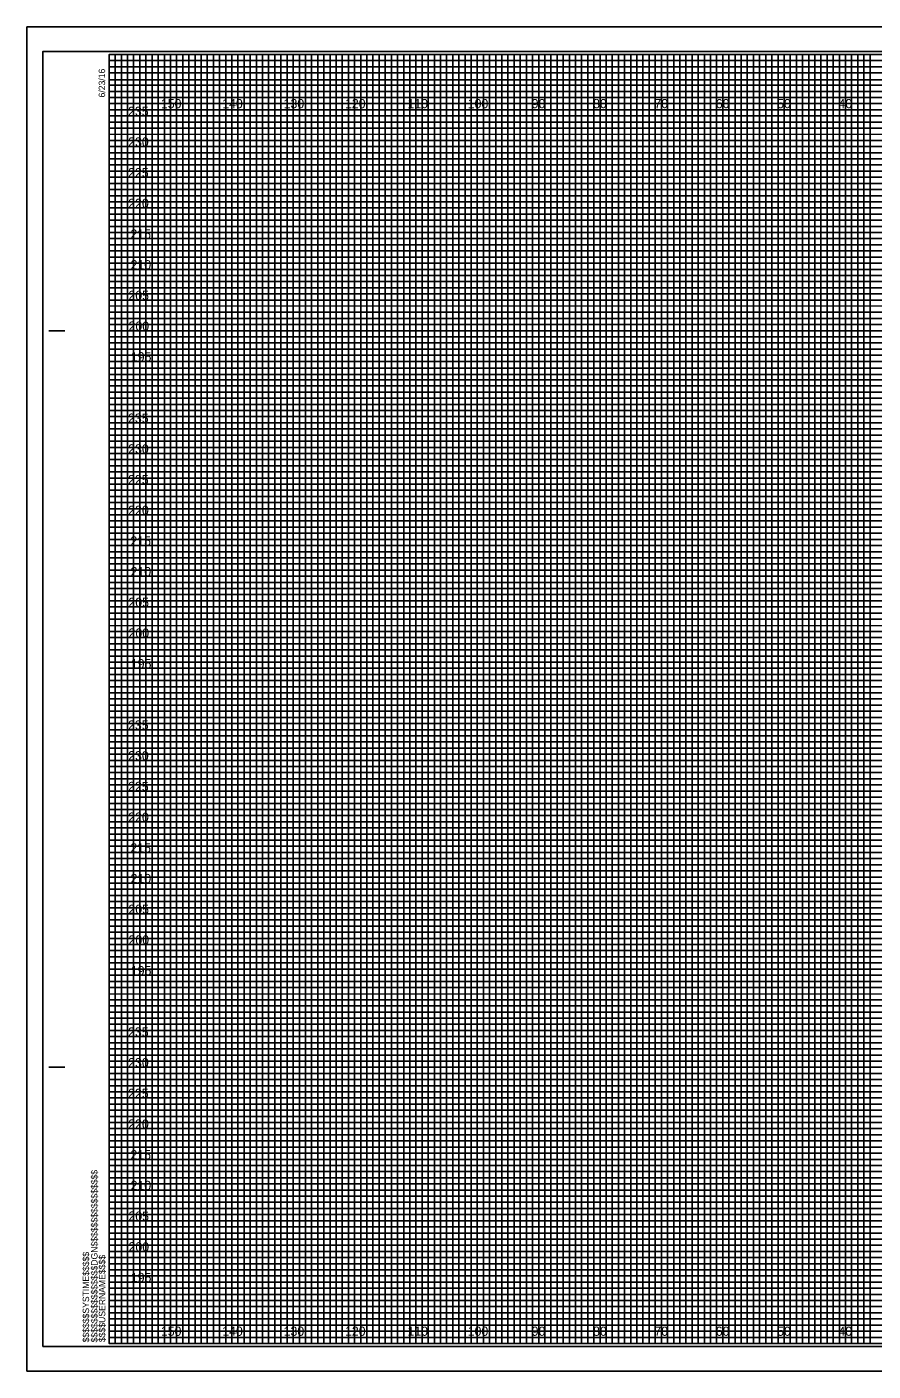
# Model space of a CAD drawing. Extents: x -13 to 323, y -5 to 434.
# Drawn here: x -13.4 to 124.5, y -4.5 to 214.5 of the extents above; entities that cross this region are included whole.
import ezdxf

# ---------------------------------------------------------------- set-up
doc = ezdxf.new("R2010")
doc.units = 0
for name, color, linetype in [('Prop XS Elevation Labels', 7, 'Continuous'), ('Prop XS Offset Labels', 7, 'Continuous'), ('Sheet Cross Section CELL', 7, 'Continuous'), ('Sheet Cross Section Grid Major CELL', 7, 'Continuous'), ('Sheet Cross Section Grid Middle CELL', 7, 'Continuous'), ('Sheet Cross Section Grid Minor 1 CELL', 7, 'Continuous'), ('Sheet Cross Section Grid Minor 2 CELL', 7, 'Continuous'), ('Sheet Cutting Line CELL', 7, 'Continuous'), ('Sheet DOT Grid CELL', 7, 'Continuous'), ('Sheet Plot Border Inside CELL', 7, 'Continuous'), ('Sheet Plot Border Outside CELL', 7, 'Continuous')]:
    doc.layers.add(name, color=color, linetype=linetype)

msp = doc.modelspace()

# ---------------------------------------------------------------- linework, layer by layer
at = {"layer": 'Sheet Cross Section CELL'}
for p, q in [((-9.8, 165), (-7.3, 165)), ((-9.7, 165), (-7.2, 165)), ((-9.8, 45), (-7.3, 45)), ((-9.7, 45), (-7.2, 45)), ((0, 0), (0, 0)), ((0, 0), (0, 0)), ((0, 0), (0, 0)), ((0, 0), (0, 0)), ((0, 0), (0, 0)), ((0, 0), (0, 0)), ((0, 0), (0, 0))]:
    msp.add_line(p, q, dxfattribs=at)
msp.add_lwpolyline([(320, 210), (0, 210), (0, 0), (320, 0)], close=True, dxfattribs=at)
at = {"layer": 'Sheet Cross Section Grid Major CELL'}
for p, q in [((10, 210), (0, 210)), ((10, 0), (10, 210)), ((30, 210), (20, 210)), ((20, 210), (20, 0)), ((30, 0), (30, 210)), ((50, 210), (40, 210)), ((40, 210), (40, 0)), ((50, 0), (50, 210)), ((70, 210), (60, 210)), ((60, 210), (60, 0)), ((70, 0), (70, 210)), ((90, 210), (80, 210)), ((80, 210), (80, 0)), ((90, 0), (90, 210)), ((110, 210), (100, 210)), ((100, 210), (100, 0)), ((110, 0), (110, 210)), ((130, 210), (120, 210)), ((120, 210), (120, 0)), ((20, 0), (10, 0)), ((40, 0), (30, 0)), ((60, 0), (50, 0)), ((80, 0), (70, 0)), ((100, 0), (90, 0)), ((120, 0), (110, 0))]:
    msp.add_line(p, q, dxfattribs=at)
for points in [[(0, 200), (320, 200), (320, 190), (0, 190)], [(0, 180), (320, 180), (320, 170), (0, 170)], [(0, 160), (320, 160), (320, 150), (0, 150)], [(0, 140), (320, 140), (320, 130), (0, 130)], [(0, 120), (320, 120), (320, 110), (0, 110)], [(0, 100), (320, 100), (320, 90), (0, 90)], [(0, 80), (320, 80), (320, 70), (0, 70)], [(0, 60), (320, 60), (320, 50), (0, 50)], [(0, 40), (320, 40), (320, 30), (0, 30)], [(0, 20), (320, 20), (320, 10), (0, 10)]]:
    msp.add_lwpolyline(points, dxfattribs=at)
at = {"layer": 'Sheet Cross Section Grid Middle CELL'}
for points in [[(0, 210), (5, 210), (5, 0), (15, 0), (15, 210), (25, 210), (25, 0), (35, 0), (35, 210), (45, 210), (45, 0), (55, 0), (55, 210), (65, 210), (65, 0), (75, 0), (75, 210), (85, 210), (85, 0), (95, 0), (95, 210), (105, 210), (105, 0), (115, 0), (115, 210), (125, 210)], [(0, 205), (275, 205)], [(0, 185), (320, 185), (320, 195), (0, 195)], [(0, 165), (320, 165), (320, 175), (0, 175)], [(0, 145), (320, 145), (320, 155), (0, 155)], [(0, 125), (320, 125), (320, 135), (0, 135)], [(0, 105), (320, 105), (320, 115), (0, 115)], [(0, 85), (320, 85), (320, 95), (0, 95)], [(0, 65), (320, 65), (320, 75), (0, 75)], [(0, 45), (320, 45), (320, 55), (0, 55)], [(0, 25), (320, 25), (320, 35), (0, 35)], [(0, 5), (320, 5), (320, 15), (0, 15)]]:
    msp.add_lwpolyline(points, dxfattribs=at)
at = {"layer": 'Sheet Cross Section Grid Minor 1 CELL'}
for p, q in [((0, 209), (260, 209)), ((260, 207.98), (0, 207.98)), ((0, 207.98), (0, 207)), ((0, 207), (260, 207)), ((260, 205.89), (0, 205.89)), ((0, 205.89), (0, 204)), ((0, 204), (320, 204))]:
    msp.add_line(p, q, dxfattribs=at)
for points in [[(0, 203), (270, 203), (320, 203), (320, 202), (0, 202)], [(0, 201), (320, 201), (320, 199), (0, 199)], [(0, 198), (320, 198), (320, 197), (0, 196.98)], [(0, 196), (320, 196), (320, 194), (0, 194)], [(0, 193), (320, 193), (320, 192), (0, 192)], [(0, 191), (320, 191), (320, 189), (0, 189)], [(0, 188), (320, 188), (320, 187), (0, 187)], [(0, 186), (320, 186), (320, 184), (0, 184)], [(0, 183), (320, 183), (320, 182), (0, 182)], [(0, 181), (320, 181), (320, 179), (0, 179)], [(0, 178), (320, 178), (320, 177), (0, 177)], [(0, 176), (320, 176), (320, 173.95), (320, 173), (320, 172), (0, 172)], [(0, 174), (320, 174), (320, 173), (0, 173)], [(0, 171), (320, 171), (320, 169), (0, 169.03)], [(0, 169.03), (320, 169), (320, 168), (0, 168)], [(0, 167), (320, 167), (320, 166), (0, 166)], [(0, 164), (320, 164), (320, 163), (0, 163)], [(0, 162), (320, 162), (320, 161), (0, 161)], [(-0.07, 158.89), (320, 158.89), (320, 157.88), (-0.07, 157.88)], [(0, 157), (320, 157), (320, 156), (0, 156)], [(0, 154), (320, 154), (320, 153), (0, 153)], [(0, 152), (320, 152), (320, 151), (0, 151)], [(0, 149), (320, 149), (320, 148), (0, 148)], [(0, 147), (320, 147), (320, 146), (0, 146)], [(0, 144), (320, 144), (320, 143), (0, 143)], [(0, 142), (320, 142), (320, 141), (0, 141)], [(0, 139), (320, 139), (319.99, 137.98), (0, 138)], [(0, 137), (320, 137), (320, 136), (0, 136)], [(0, 134), (320, 134), (320, 133), (0, 133)], [(0, 132), (320, 132), (320, 131), (0, 131)], [(0, 129), (320, 129), (320, 128), (0, 128)], [(0, 127), (320, 127), (320, 126), (0, 126)], [(0, 124), (320, 124), (320, 123), (0, 123)], [(0, 122), (320, 122), (320, 121), (0, 121)], [(0, 119), (320, 119), (320, 118), (0, 118)], [(0, 116.99), (320.07, 116.91), (320, 116), (0, 116)], [(0, 114), (320, 114), (320, 113), (0, 113)], [(0, 112), (320, 112), (320, 111), (0, 111)], [(0, 109), (320, 109), (320, 108), (0, 108)], [(0, 107), (320, 107), (320, 106), (0, 106)], [(0, 104), (320, 104), (320, 103), (0, 103)], [(0, 102), (320, 102), (320, 101), (0, 101)], [(0, 99), (320, 99), (320, 98), (0, 98)], [(0, 97), (320, 97), (320, 96), (0, 96)], [(0, 94), (320, 94), (320, 93), (0, 93)], [(0, 92), (320, 92), (320, 91), (0, 91)], [(0, 89), (320, 89), (320, 88), (0, 88)], [(0, 87), (320, 87), (320, 86), (0, 86)], [(0, 84), (320, 84), (320, 83), (0, 83)], [(0, 82), (320, 82), (320, 81), (0, 81)], [(0, 79), (320, 79), (319.99, 77.98), (0, 78)], [(0, 77), (320, 77), (320, 76), (0, 76)], [(0, 74), (320, 74), (320, 73), (0, 73)], [(0, 72), (320, 72), (320, 71), (0, 71)], [(0, 69), (320, 69), (320, 68), (0, 68)], [(0, 67), (320, 67), (320, 66), (0, 66)], [(0, 64), (320, 64), (320, 63), (0, 63)], [(0, 62), (320, 62), (320, 61), (0, 61)], [(0, 59), (320, 59), (320, 58), (0, 58)], [(0, 56.99), (320.07, 56.91), (320, 56), (0, 56)], [(0, 54), (320, 54), (320, 53), (0, 53)], [(0, 52), (320, 52), (320, 51), (0, 51)], [(0, 49), (320, 49), (320, 48), (0, 48)], [(0, 47), (320, 47), (320, 46), (0, 46)], [(0, 44), (320, 44), (320, 43), (0, 43)], [(0, 42), (320, 42), (320, 41), (0, 41)], [(0, 39), (320, 39), (320, 38), (0, 38)], [(0, 37), (320, 37), (320, 36), (0, 36)], [(0, 34), (320, 34), (320, 33), (0, 33)], [(0, 32), (320, 32), (320, 31), (0, 31)], [(0, 29), (320, 29), (320, 28), (0, 28)], [(0, 27), (320, 27), (320, 26), (0, 26)], [(0, 24), (320, 24), (320, 23), (0, 23)], [(0, 22), (320, 22), (320, 21), (0, 21)], [(0, 19), (320, 19), (320, 18), (0, 18)], [(0, 17), (320, 17), (320, 16), (0, 16)], [(0, 14), (320, 14), (320, 13), (0, 13)], [(0, 12), (320, 12), (320, 11), (0, 11)], [(0, 9), (320, 9), (320, 8), (0, 8)], [(0, 7), (320, 7), (320, 6), (0, 6)], [(0, 4), (320, 4), (320, 3), (0, 3)], [(0, 2), (320, 2), (320, 1), (0, 1)]]:
    msp.add_lwpolyline(points, dxfattribs=at)
at = {"layer": 'Sheet Cross Section Grid Minor 2 CELL'}
for points in [[(0, 0), (1, 0), (1, 210), (2, 210), (2, 0)], [(2, 0), (3, 0), (3, 210), (4, 210), (4, 0)], [(5, 0), (6, 0), (6, 210), (7, 210), (7, 0)], [(7, 0), (8, 0), (8, 210), (9, 210), (9, 0)], [(10, 0), (11, 0), (11, 210), (12, 210), (12, 0)], [(12, 0), (13, 0), (13, 210), (14, 210), (14, 0)], [(15, 0), (16, 0), (16, 210), (17, 210), (17, 0)], [(17, 0), (18, 0), (18, 210), (19, 210), (19, 0)], [(20, 0), (21, 0), (21, 210), (22, 210), (22, 0)], [(22, 0), (23, 0), (23, 210), (24, 210), (24, 0)], [(25, 0), (26, 0), (26, 210), (27, 210), (27, 0)], [(27, 0), (28, 0), (28, 210), (29, 210), (29, 0)], [(30, 0), (31, 0), (31, 210), (32, 210), (32, 0)], [(32, 0), (33, 0), (33, 210), (34, 210), (34, 0)], [(35, 0), (36, 0), (36, 210), (37, 210), (37, 0)], [(37, 0), (38, 0), (38, 210), (39, 210), (39, 0)], [(40, 0), (41, 0), (41, 210), (42, 210), (42, 0)], [(42, 0), (43, 0), (43, 210), (44, 210), (44, 0)], [(45, 0), (46, 0), (46, 210), (47, 210), (47, 0)], [(47, 0), (48, 0), (48, 210), (49, 210), (49, 0)], [(50, 0), (51, 0), (51, 210), (52, 210), (52, 0)], [(52, 0), (53, 0), (53, 210), (54, 210), (54, 0)], [(55, 0), (56, 0), (56, 210), (57, 210), (57, 0)], [(57, 0), (58, 0), (58, 210), (59, 210), (59, 0)], [(60, 0), (61, 0), (61, 210), (62, 210), (62, 0)], [(62, 0), (63, 0), (63, 210), (64, 210), (64, 0)], [(65, 0), (66, 0), (66, 210), (67, 210), (67, 0)], [(67, 0), (68, 0), (68, 210), (69, 210), (69, 0)], [(70, 0), (71, 0), (71, 210), (72, 210), (72, 0)], [(72, 0), (73, 0), (73, 210), (74, 210), (74, 0)], [(75, 0), (76, 0), (76, 210), (77, 210), (77, 0)], [(77, 0), (78, 0), (78, 210), (79, 210), (79, 0)], [(80, 0), (81, 0), (81, 210), (82, 210), (82, 0)], [(82, 0), (83, 0), (83, 210), (84, 210), (84, 0)], [(85, 0), (86, 0), (86, 210), (87, 210), (87, 0)], [(87, 0), (88, 0), (88, 210), (89, 210), (89, 0)], [(90, 0), (91, 0), (91, 210), (92, 210), (92, 0)], [(92, 0), (93, 0), (93, 210), (94, 210), (94, 0)], [(95, 0), (96, 0), (96, 210), (97, 210), (97, 0)], [(97, 0), (98, 0), (98, 210), (99, 210), (99, 0)], [(100, 0), (101, 0), (101, 210), (102, 210), (102, 0)], [(102, 0), (103, 0), (103, 210), (104, 210), (104, 0)], [(105, 0), (106, 0), (106, 210), (107, 210), (107, 0)], [(107, 0), (108, 0), (108, 210), (109, 210), (109, 0)], [(110, 0), (111, 0), (111, 210), (112, 210), (112, 0)], [(112, 0), (113, 0), (113, 210), (114, 210), (114, 0)], [(115, 0), (116, 0), (116, 210), (117, 210), (117, 0)], [(117, 0), (118, 0), (118, 210), (119, 210), (119, 0)], [(120, 0), (121, 0), (121, 210), (122, 210), (122, 0)], [(122, 0), (123, 0), (123, 210), (124, 210), (124, 0)]]:
    msp.add_lwpolyline(points, dxfattribs=at)
at = {"layer": 'Sheet Cutting Line CELL'}
for p, q in [((323.3, 214.5), (-13.4, 214.5)), ((-13.4, 214.5), (-13.4, -4.5)), ((-13.4, -4.5), (323.3, -4.5))]:
    msp.add_line(p, q, dxfattribs=at)
at = {"layer": 'Sheet DOT Grid CELL'}
for p, q in [((10, 0), (10, 210)), ((20, 0), (20, 210)), ((30, 0), (30, 210)), ((40, 0), (40, 210)), ((50, 0), (50, 210)), ((60, 0), (60, 210)), ((70, 0), (70, 210)), ((80, 0), (80, 210)), ((90, 0), (90, 210)), ((100, 0), (100, 210)), ((110, 0), (110, 210)), ((120, 0), (120, 210)), ((0, 200), (320, 200)), ((0, 190), (320, 190)), ((0, 180), (320, 180)), ((0, 170), (320, 170)), ((0, 160), (320, 160)), ((0, 150), (320, 150)), ((0, 140), (320, 140)), ((0, 130), (320, 130)), ((0, 120), (320, 120)), ((0, 110), (320, 110)), ((0, 100), (320, 100)), ((0, 90), (320, 90)), ((0, 80), (320, 80)), ((0, 70), (320, 70)), ((0, 60), (320, 60)), ((0, 50), (320, 50)), ((0, 40), (320, 40)), ((0, 30), (320, 30)), ((0, 20), (320, 20)), ((0, 10), (320, 10))]:
    msp.add_line(p, q, dxfattribs=at)
at = {"layer": 'Sheet Plot Border Inside CELL'}
msp.add_lwpolyline([(-10.8, -0.5), (322.4, -0.5), (322.4, 210.5), (-10.8, 210.5)], close=True, dxfattribs=at)
at = {"layer": 'Sheet Plot Border Outside CELL'}
msp.add_lwpolyline([(-13.4, -4.5), (323.3, -4.5), (323.3, 214.5), (-13.4, 214.5)], close=True, dxfattribs=at)

# ---------------------------------------------------------------- texts
at = {"layer": 'Prop XS Elevation Labels'}
for s, p in [('235', (3.09, 200)), ('230', (3.11, 195)), ('225', (3.1, 190)), ('220', (3.12, 185)), ('215', (3.48, 180)), ('210', (3.5, 175)), ('205', (3.15, 170)), ('200', (3.17, 165)), ('195', (3.55, 160)), ('235', (3.09, 150)), ('230', (3.11, 145)), ('225', (3.1, 140)), ('220', (3.12, 135)), ('215', (3.48, 130)), ('210', (3.5, 125)), ('205', (3.15, 120)), ('200', (3.17, 115)), ('195', (3.55, 110)), ('235', (3.09, 100)), ('230', (3.11, 95)), ('225', (3.1, 90)), ('220', (3.12, 85)), ('215', (3.48, 80)), ('210', (3.5, 75)), ('205', (3.15, 70)), ('200', (3.17, 65)), ('195', (3.55, 60)), ('235', (3.09, 50)), ('230', (3.11, 45)), ('225', (3.1, 40)), ('220', (3.12, 35)), ('215', (3.48, 30)), ('210', (3.5, 25)), ('205', (3.15, 20)), ('200', (3.17, 15)), ('195', (3.55, 10))]:
    msp.add_text(s, height=1.5, dxfattribs=at).set_placement(p)
at = {"layer": 'Prop XS Offset Labels'}
for s, p in [('150', (8.44, 201.25)), ('140', (18.44, 201.25)), ('130', (28.44, 201.25)), ('120', (38.44, 201.25)), ('110', (48.62, 201.25)), ('100', (58.44, 201.25)), ('90', (68.86, 201.25)), ('80', (78.86, 201.25)), ('70', (88.86, 201.25)), ('60', (98.86, 201.25)), ('50', (108.86, 201.25)), ('40', (118.86, 201.25)), ('150', (8.44, 1.25)), ('140', (18.44, 1.25)), ('130', (28.44, 1.25)), ('120', (38.44, 1.25)), ('110', (48.62, 1.25)), ('100', (58.44, 1.25)), ('90', (68.86, 1.25)), ('80', (78.86, 1.25)), ('70', (88.86, 1.25)), ('60', (98.86, 1.25)), ('50', (108.86, 1.25)), ('40', (118.86, 1.25))]:
    msp.add_text(s, height=1.5, dxfattribs=at).set_placement(p)
at = {"layer": 'Sheet Cross Section CELL'}
for s, p in [('6/23/16', (-0.65, 203)), ('$$$$$$$$$$$$$$$$DGN$$$$$$$$$$$$$$$$', (-1.88, 0.18)), ('$$$$$$SYSTIME$$$$$', (-3.26, 0.18)), ('$$$$USERNAME$$$$', (-0.62, 0.23))]:
    msp.add_text(s, height=1.05, rotation=90, dxfattribs=at).set_placement(p)

doc.saveas('drawing.dxf')
